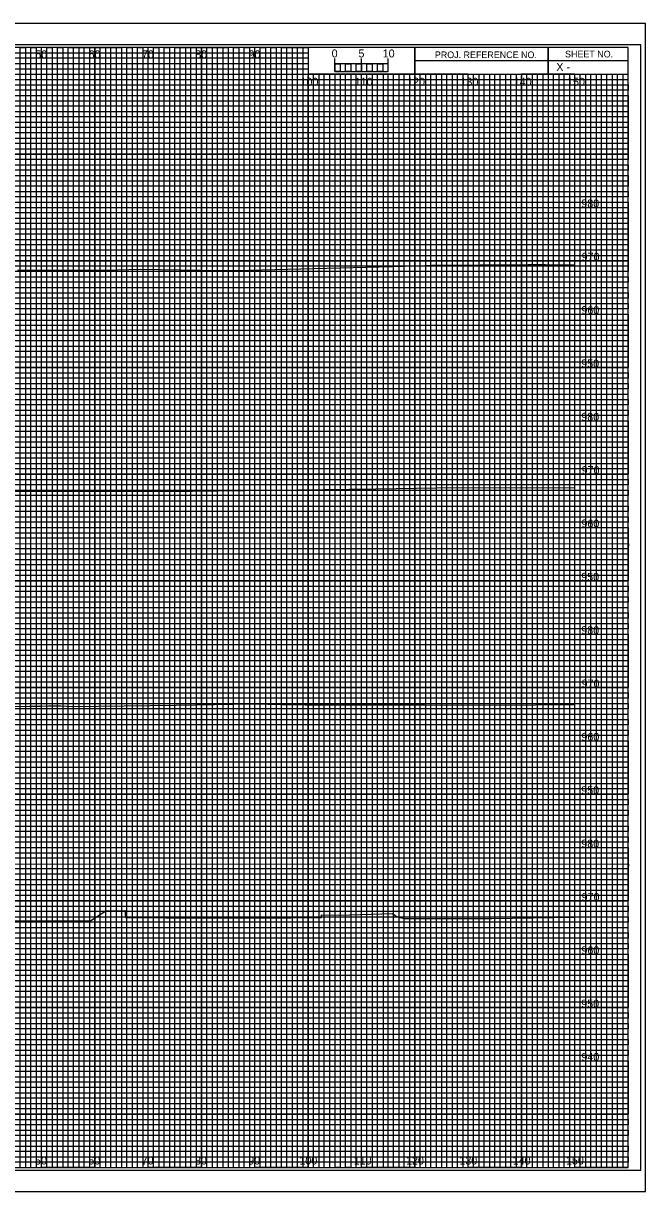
# Model space of a CAD drawing. Extents: x -13 to 760, y -5 to 1491.
# Drawn here: x 206.6 to 323.3, y 952.5 to 1171.5 of the extents above; entities that cross this region are included whole.
import ezdxf

# ---------------------------------------------------------------- set-up
doc = ezdxf.new("R2010")
doc.units = 0
for name, color, linetype in [('Exist XS Ground Line', 7, 'Continuous'), ('Prop XS Elevation Labels', 7, 'Continuous'), ('Prop XS Offset Labels', 7, 'Continuous'), ('Sheet Cross Section CELL', 7, 'Continuous'), ('Sheet Cross Section Grid Major CELL', 7, 'Continuous'), ('Sheet Cross Section Grid Middle CELL', 7, 'Continuous'), ('Sheet Cross Section Grid Minor 1 CELL', 7, 'Continuous'), ('Sheet Cross Section Grid Minor 2 CELL', 7, 'Continuous'), ('Sheet Cross Section Scale CELL', 7, 'Continuous'), ('Sheet Cutting Line CELL', 7, 'Continuous'), ('Sheet DOT Grid CELL', 7, 'Continuous'), ('Sheet Plot Border Inside CELL', 7, 'Continuous'), ('Sheet Plot Border Outside CELL', 7, 'Continuous')]:
    doc.layers.add(name, color=color, linetype=linetype)

msp = doc.modelspace()

# ---------------------------------------------------------------- linework, layer by layer
at = {"layer": 'Exist XS Ground Line'}
for points in [[(205.5, 1125.24), (224.22, 1125.32), (228.53, 1125.43), (243.78, 1125.18), (245.43, 1125.17), (245.61, 1125.17), (246.42, 1125.17), (280.64, 1126.05), (283.2, 1126.18), (301.24, 1126.32), (302.72, 1126.34), (304.49, 1126.33), (310, 1126.25)], [(205.5, 1125.24), (224.22, 1125.32), (228.53, 1125.43), (243.78, 1125.18), (245.43, 1125.17), (245.61, 1125.17), (246.42, 1125.17), (280.64, 1126.05), (283.2, 1126.18), (301.24, 1126.32), (302.72, 1126.34), (304.49, 1126.33), (310, 1126.25)], [(188.63, 1083.76), (217.55, 1083.82), (233.39, 1083.79), (272.72, 1084.24), (284.14, 1084.47), (295.83, 1084.5), (310, 1084.46)], [(188.63, 1083.76), (217.55, 1083.82), (233.39, 1083.79), (272.72, 1084.24), (284.14, 1084.47), (295.83, 1084.5), (310, 1084.46)], [(196.8, 1043.44), (207.77, 1043.51), (210.05, 1043.53), (211.28, 1043.58), (213.62, 1043.59), (215.73, 1043.45), (235.24, 1043.73), (249.69, 1043.94), (255.11, 1043.83), (259.43, 1043.79), (267.91, 1043.74), (281.85, 1043.74), (284.81, 1043.7), (288.81, 1043.8), (295.24, 1043.7), (310, 1043.83)], [(196.8, 1043.44), (207.77, 1043.51), (210.05, 1043.53), (211.28, 1043.58), (213.62, 1043.59), (215.73, 1043.45), (235.24, 1043.73), (249.69, 1043.94), (255.11, 1043.83), (259.43, 1043.79), (267.91, 1043.74), (281.85, 1043.74), (284.81, 1043.7), (288.81, 1043.8), (295.24, 1043.7), (310, 1043.83)], [(201.56, 1003.28), (219.24, 1003.32), (222.07, 1005.14), (222.08, 1005.14), (222.18, 1005.14), (225.68, 1005.22), (225.71, 1004.61), (225.77, 1003.89), (225.78, 1003.89), (228.27, 1003.88), (233.32, 1003.85), (256.76, 1003.85), (262.47, 1003.88), (262.48, 1003.88), (262.51, 1004.43), (265.79, 1004.32), (275.8, 1004.67), (276.7, 1004.01), (278.04, 1003.7), (294.46, 1003.69), (310, 1003.97)], [(201.56, 1003.28), (219.24, 1003.32), (222.07, 1005.14), (222.08, 1005.14), (222.18, 1005.14), (225.68, 1005.22), (225.71, 1004.61), (225.77, 1003.89), (225.78, 1003.89), (228.27, 1003.88), (233.32, 1003.85), (256.76, 1003.85), (262.47, 1003.88), (262.48, 1003.88), (262.51, 1004.43), (265.79, 1004.32), (275.8, 1004.67), (276.7, 1004.01), (278.04, 1003.7), (294.46, 1003.69), (310, 1003.97)]]:
    msp.add_lwpolyline(points, dxfattribs=at)
at = {"layer": 'Sheet Cross Section CELL'}
for p, q in [((305, 1167.01), (305, 1162.01)), ((305, 1162.01), (305, 1167.01)), ((280, 1164.51), (280, 1162.01)), ((320, 1164.5), (280, 1164.5)), ((280, 1162.01), (320, 1162.01))]:
    msp.add_line(p, q, dxfattribs=at)
for points in [[(320, 1167.01), (0, 1167.01), (0, 957.01), (320, 957.01)], [(280, 1167.01), (260, 1167.01), (260, 1162.04), (280, 1162.04)], [(320, 1167.01), (280, 1167.01), (280, 1162.01), (320, 1162.01)]]:
    msp.add_lwpolyline(points, close=True, dxfattribs=at)
at = {"layer": 'Sheet Cross Section Grid Major CELL'}
for p, q in [((210, 1167.01), (200, 1167.01)), ((210, 957.01), (210, 1167.01)), ((230, 1167.01), (220, 1167.01)), ((220, 1167.01), (220, 957.01)), ((230, 957.01), (230, 1167.01)), ((250, 1167.01), (240, 1167.01)), ((240, 1167.01), (240, 957.01)), ((250, 957.01), (250, 1167.01)), ((260, 1167.01), (260, 957.01)), ((270, 957.01), (270, 1162.01)), ((290, 1162.01), (280, 1162.01)), ((280, 1162.01), (280, 957.01)), ((290, 957.01), (290, 1162.01)), ((310, 1162.01), (300, 1162.01)), ((300, 1162.01), (300, 957.01)), ((310, 957.01), (310, 1162.01)), ((220, 957.01), (210, 957.01)), ((240, 957.01), (230, 957.01)), ((260, 957.01), (250, 957.01)), ((280, 957.01), (270, 957.01)), ((300, 957.01), (290, 957.01)), ((320, 957.01), (310, 957.01)), ((320, 957.01), (320, 957.01))]:
    msp.add_line(p, q, dxfattribs=at)
for points in [[(0, 1157.01), (320, 1157.01), (320, 1147.01), (0, 1147.01)], [(0, 1137.01), (320, 1137.01), (320, 1127.01), (0, 1127.01)], [(0, 1117.01), (320, 1117.01), (320, 1107.01), (0, 1107.01)], [(0, 1097.01), (320, 1097.01), (320, 1087.01), (0, 1087.01)], [(0, 1077.01), (320, 1077.01), (320, 1067.01), (0, 1067.01)], [(0, 1057.01), (320, 1057.01), (320, 1047.01), (0, 1047.01)], [(0, 1037.01), (320, 1037.01), (320, 1027.01), (0, 1027.01)], [(0, 1017.01), (320, 1017.01), (320, 1007.01), (0, 1007.01)], [(0, 997.01), (320, 997.01), (320, 987.01), (0, 987.01)], [(0, 977.01), (320, 977.01), (320, 967.01), (0, 967.01)]]:
    msp.add_lwpolyline(points, dxfattribs=at)
at = {"layer": 'Sheet Cross Section Grid Middle CELL'}
for points in [[(205, 957.01), (215, 957.01), (215, 1167.01), (225, 1167.01), (225, 957.01), (235, 957.01), (235, 1167.01), (245, 1167.01), (245, 957.01), (255, 957.01), (255, 1167.01), (259.93, 1167.01), (260, 1167.01), (260, 1162.01), (264.99, 1162.01), (264.99, 957.01), (275, 957.01), (275, 1162.01), (285, 1162.01), (285, 957.01), (295, 957.01), (295, 1162.01), (305, 1162.01), (305, 957.01), (315, 957.01), (315, 1162.01)], [(0, 1162.01), (275, 1162.01)], [(0, 1142.01), (320, 1142.01), (320, 1152.01), (0, 1152.01)], [(0, 1122.01), (320, 1122.01), (320, 1132.01), (0, 1132.01)], [(0, 1102.01), (320, 1102.01), (320, 1112.01), (0, 1112.01)], [(0, 1082.01), (320, 1082.01), (320, 1092.01), (0, 1092.01)], [(0, 1062.01), (320, 1062.01), (320, 1072.01), (0, 1072.01)], [(0, 1042.01), (320, 1042.01), (320, 1052.01), (0, 1052.01)], [(0, 1022.01), (320, 1022.01), (320, 1032.01), (0, 1032.01)], [(0, 1002.01), (320, 1002.01), (320, 1012.01), (0, 1012.01)], [(0, 982.01), (320, 982.01), (320, 992.01), (0, 992.01)], [(0, 962.01), (320, 962.01), (320, 972.01), (0, 972.01)]]:
    msp.add_lwpolyline(points, dxfattribs=at)
at = {"layer": 'Sheet Cross Section Grid Minor 1 CELL'}
for p, q in [((0, 1166.01), (260, 1166.01)), ((260, 1166.01), (260, 1164.99)), ((260, 1164.99), (0, 1164.99)), ((0, 1164.01), (260, 1164.01)), ((260, 1162.9), (0, 1162.9)), ((260, 1164.01), (260, 1162.9)), ((0, 1161.01), (320, 1161.01))]:
    msp.add_line(p, q, dxfattribs=at)
for points in [[(0, 1160.01), (270, 1160.01), (320, 1160.01), (320, 1159.01), (0, 1159.01)], [(0, 1158.01), (320, 1158.01), (320, 1156.01), (0, 1156.01)], [(0, 1155.01), (320, 1155.01), (320, 1154.01), (0, 1153.99)], [(0, 1153.01), (320, 1153.01), (320, 1151.01), (0, 1151.01)], [(0, 1150.01), (320, 1150.01), (320, 1149.01), (0, 1149.01)], [(0, 1148.01), (320, 1148.01), (320, 1146.01), (0, 1146.01)], [(0, 1145.01), (320, 1145.01), (320, 1144.01), (0, 1144.01)], [(0, 1143.01), (320, 1143.01), (320, 1141.01), (0, 1141.01)], [(0, 1140.01), (320, 1140.01), (320, 1139.01), (0, 1139.01)], [(0, 1138.01), (320, 1138.01), (320, 1136.01), (0, 1136.01)], [(0, 1135.01), (320, 1135.01), (320, 1134.01), (0, 1134.01)], [(0, 1133.01), (320, 1133.01), (320, 1130.96), (320, 1130.01), (320, 1129.01), (0, 1129.01)], [(0, 1131.01), (320, 1131.01), (320, 1130.01), (0, 1130.01)], [(0, 1128.01), (320, 1128.01), (320, 1126.01), (0, 1126.04)], [(0, 1126.04), (320, 1126.01), (320, 1125.01), (0, 1125.01)], [(0, 1124.01), (320, 1124.01), (320, 1123.01), (0, 1123.01)], [(0, 1121.01), (320, 1121.01), (320, 1120.01), (0, 1120.01)], [(0, 1119.01), (320, 1119.01), (320, 1118.01), (0, 1118.01)], [(-0.07, 1115.9), (320, 1115.9), (320, 1114.89), (-0.07, 1114.89)], [(0, 1114.01), (320, 1114.01), (320, 1113.01), (0, 1113.01)], [(0, 1111.01), (320, 1111.01), (320, 1110.01), (0, 1110.01)], [(0, 1109.01), (320, 1109.01), (320, 1108.01), (0, 1108.01)], [(0, 1106.01), (320, 1106.01), (320, 1105.01), (0, 1105.01)], [(0, 1104.01), (320, 1104.01), (320, 1103.01), (0, 1103.01)], [(0, 1101.01), (320, 1101.01), (320, 1100.01), (0, 1100.01)], [(0, 1099.01), (320, 1099.01), (320, 1098.01), (0, 1098.01)], [(0, 1096.01), (320, 1096.01), (319.99, 1094.99), (0, 1095.01)], [(0, 1094.01), (320, 1094.01), (320, 1093.01), (0, 1093.01)], [(0, 1091.01), (320, 1091.01), (320, 1090.01), (0, 1090.01)], [(0, 1089.01), (320, 1089.01), (320, 1088.01), (0, 1088.01)], [(0, 1086.01), (320, 1086.01), (320, 1085.01), (0, 1085.01)], [(0, 1084.01), (320, 1084.01), (320, 1083.01), (0, 1083.01)], [(0, 1081.01), (320, 1081.01), (320, 1080.01), (0, 1080.01)], [(0, 1079.01), (320, 1079.01), (320, 1078.01), (0, 1078.01)], [(0, 1076.01), (320, 1076.01), (320, 1075.01), (0, 1075.01)], [(0, 1074), (320.07, 1073.92), (320, 1073.01), (0, 1073.01)], [(0, 1071.01), (320, 1071.01), (320, 1070.01), (0, 1070.01)], [(0, 1069.01), (320, 1069.01), (320, 1068.01), (0, 1068.01)], [(0, 1066.01), (320, 1066.01), (320, 1065.01), (0, 1065.01)], [(0, 1064.01), (320, 1064.01), (320, 1063.01), (0, 1063.01)], [(0, 1061.01), (320, 1061.01), (320, 1060.01), (0, 1060.01)], [(0, 1059.01), (320, 1059.01), (320, 1058.01), (0, 1058.01)], [(0, 1056.01), (320, 1056.01), (320, 1055.01), (0, 1055.01)], [(0, 1054.01), (320, 1054.01), (320, 1053.01), (0, 1053.01)], [(0, 1051.01), (320, 1051.01), (320, 1050.01), (0, 1050.01)], [(0, 1049.01), (320, 1049.01), (320, 1048.01), (0, 1048.01)], [(0, 1046.01), (320, 1046.01), (320, 1045.01), (0, 1045.01)], [(0, 1044.01), (320, 1044.01), (320, 1043.01), (0, 1043.01)], [(0, 1041.01), (320, 1041.01), (320, 1040.01), (0, 1040.01)], [(0, 1039.01), (320, 1039.01), (320, 1038.01), (0, 1038.01)], [(0, 1036.01), (320, 1036.01), (319.99, 1034.99), (0, 1035.01)], [(0, 1034.01), (320, 1034.01), (320, 1033.01), (0, 1033.01)], [(0, 1031.01), (320, 1031.01), (320, 1030.01), (0, 1030.01)], [(0, 1029.01), (320, 1029.01), (320, 1028.01), (0, 1028.01)], [(0, 1026.01), (320, 1026.01), (320, 1025.01), (0, 1025.01)], [(0, 1024.01), (320, 1024.01), (320, 1023.01), (0, 1023.01)], [(0, 1021.01), (320, 1021.01), (320, 1020.01), (0, 1020.01)], [(0, 1019.01), (320, 1019.01), (320, 1018.01), (0, 1018.01)], [(0, 1016.01), (320, 1016.01), (320, 1015.01), (0, 1015.01)], [(0, 1014), (320.07, 1013.92), (320, 1013.01), (0, 1013.01)], [(0, 1011.01), (320, 1011.01), (320, 1010.01), (0, 1010.01)], [(0, 1009.01), (320, 1009.01), (320, 1008.01), (0, 1008.01)], [(0, 1006.01), (320, 1006.01), (320, 1005.01), (0, 1005.01)], [(0, 1004.01), (320, 1004.01), (320, 1003.01), (0, 1003.01)], [(0, 1001.01), (320, 1001.01), (320, 1000.01), (0, 1000.01)], [(0, 999.01), (320, 999.01), (320, 998.01), (0, 998.01)], [(0, 996.01), (320, 996.01), (320, 995.01), (0, 995.01)], [(0, 994.01), (320, 994.01), (320, 993.01), (0, 993.01)], [(0, 991.01), (320, 991.01), (320, 990.01), (0, 990.01)], [(0, 989.01), (320, 989.01), (320, 988.01), (0, 988.01)], [(0, 986.01), (320, 986.01), (320, 985.01), (0, 985.01)], [(0, 984.01), (320, 984.01), (320, 983.01), (0, 983.01)], [(0, 981.01), (320, 981.01), (320, 980.01), (0, 980.01)], [(0, 979.01), (320, 979.01), (320, 978.01), (0, 978.01)], [(0, 976.01), (320, 976.01), (320, 975.01), (0, 975.01)], [(0, 974.01), (320, 974.01), (320, 973.01), (0, 973.01)], [(0, 971.01), (320, 971.01), (320, 970.01), (0, 970.01)], [(0, 969.01), (320, 969.01), (320, 968.01), (0, 968.01)], [(0, 966.01), (320, 966.01), (320, 965.01), (0, 965.01)], [(0, 964.01), (320, 964.01), (320, 963.01), (0, 963.01)], [(0, 961.01), (320, 961.01), (320, 960.01), (0, 960.01)], [(0, 959.01), (320, 959.01), (320, 958.01), (0, 958.01)]]:
    msp.add_lwpolyline(points, dxfattribs=at)
at = {"layer": 'Sheet Cross Section Grid Minor 2 CELL'}
for p, q in [((267, 1162.01), (266.01, 1162.01)), ((266.01, 1162.01), (266.01, 957.01)), ((267, 957.01), (267, 1162.01)), ((269, 1162.01), (268, 1162.01)), ((268, 1162.01), (268, 957.01)), ((269, 957.01), (269, 1162.01)), ((266.01, 957.01), (265, 957.01)), ((268, 957.01), (267, 957.01))]:
    msp.add_line(p, q, dxfattribs=at)
for points in [[(205, 957.01), (206, 957.01), (206, 1167.01), (207, 1167.01), (207, 957.01)], [(207, 957.01), (208, 957.01), (208, 1167.01), (209, 1167.01), (209, 957.01)], [(210, 957.01), (211, 957.01), (211, 1167.01), (212, 1167.01), (212, 957.01)], [(212, 957.01), (213, 957.01), (213, 1167.01), (214, 1167.01), (214, 957.01)], [(215, 957.01), (216, 957.01), (216, 1167.01), (217, 1167.01), (217, 957.01)], [(217, 957.01), (218, 957.01), (218, 1167.01), (219, 1167.01), (219, 957.01)], [(220, 957.01), (221, 957.01), (221, 1167.01), (222, 1167.01), (222, 957.01)], [(222, 957.01), (223, 957.01), (223, 1167.01), (224, 1167.01), (224, 957.01)], [(225, 957.01), (226, 957.01), (226, 1167.01), (227, 1167.01), (227, 957.01)], [(227, 957.01), (228, 957.01), (228, 1167.01), (229, 1167.01), (229, 957.01)], [(230, 957.01), (231, 957.01), (231, 1167.01), (232, 1167.01), (232, 957.01)], [(232, 957.01), (233, 957.01), (233, 1167.01), (234, 1167.01), (234, 957.01)], [(235, 957.01), (236, 957.01), (236, 1167.01), (237, 1167.01), (237, 957.01)], [(237, 957.01), (238, 957.01), (238, 1167.01), (239, 1167.01), (239, 957.01)], [(240, 957.01), (241, 957.01), (241, 1167.01), (242, 1167.01), (242, 957.01)], [(242, 957.01), (243, 957.01), (243, 1167.01), (244, 1167.01), (244, 957.01)], [(245, 957.01), (246, 957.01), (246, 1167.01), (247, 1167.01), (247, 957.01)], [(247, 957.01), (248, 957.01), (248, 1167.01), (249, 1167.01), (249, 957.01)], [(250, 957.01), (251, 957.01), (251, 1167.01), (252, 1167.01), (252, 957.01)], [(252, 957.01), (253, 957.01), (253, 1167.01), (254, 1167.01), (254, 957.01)], [(255, 957.01), (256, 957.01), (256, 1167.01), (257, 1167.01), (257, 957.01)], [(257, 957.01), (258, 957.01), (258, 1167.01), (259, 1167.01), (259, 957.01)], [(260, 957.01), (261, 957.01), (261, 1162.01), (262.02, 1162.01), (262.02, 957.01)], [(262, 957.01), (263, 957.01), (263, 1162.01), (263.99, 1162.01), (263.99, 957.01)], [(270, 957.01), (270.98, 957.01), (270.98, 1162.01), (272, 1162.01), (272, 957.01)], [(272, 957.01), (273, 957.01), (273, 1162.01), (274.05, 1162.01), (274.05, 957.01)], [(275, 957.01), (276, 957.01), (276, 1162.01), (277, 1162.01), (277, 957.01)], [(277, 957.01), (278, 957.01), (278, 1162.01), (279, 1162.01), (279, 957.01)], [(280, 957.01), (281, 957.01), (281, 1162.01), (282, 1162.01), (282, 957.01)], [(282, 957.01), (283, 957.01), (283, 1162.01), (284, 1162.01), (284, 957.01)], [(285, 957.01), (286, 957.01), (286, 1162.01), (287, 1162.01), (287, 957.01)], [(287, 957.01), (288, 957.01), (288, 1162.01), (289, 1162.01), (289, 957.01)], [(290, 957.01), (291, 957.01), (291, 1162.01), (292, 1162.01), (292, 957.01)], [(292, 957.01), (293, 957.01), (293, 1162.01), (294, 1162.01), (294, 957.01)], [(295, 957.01), (296, 957.01), (296, 1162.01), (297, 1162.01), (297, 957.01)], [(297, 957.01), (298, 957.01), (298, 1162.01), (299, 1162.01), (299, 957.01)], [(300, 957.01), (301, 957.01), (301, 1162.01), (302, 1162.01), (302, 957.01)], [(302, 957.01), (303, 957.01), (303, 1162.01), (304, 1162.01), (304, 957.01)], [(305, 957.01), (306, 957.01), (306, 1162.01), (307, 1162.01), (307, 957.01)], [(307, 957.01), (308, 957.01), (308, 1162.01), (309, 1162.01), (309, 957.01)], [(310, 957.01), (311, 957.01), (311, 1162.01), (312, 1162.01), (312, 957.01)], [(312, 957.01), (313, 957.01), (313, 1162.01), (314, 1162.01), (314, 957.01)], [(315, 957.01), (316, 957.01), (316, 1162.01), (317, 1162.01), (317, 957.01)], [(317, 957.01), (318, 957.01), (318, 1162.01), (319, 1162.01), (319, 957.01)]]:
    msp.add_lwpolyline(points, dxfattribs=at)
at = {"layer": 'Sheet Cross Section Scale CELL'}
for p, q in [((265, 1162.5), (265, 1164.91)), ((265, 1163.91), (265, 1164.91)), ((270, 1162.5), (270, 1164.91)), ((275, 1162.5), (275, 1164.91)), ((275, 1163.91), (275, 1164.91))]:
    msp.add_line(p, q, dxfattribs=at)
for points in [[(275, 1163.91), (265, 1163.91), (265, 1162.5), (275, 1162.5)], [(265, 1163.91), (266, 1163.91), (266, 1162.5), (265, 1162.5)], [(267, 1163.91), (268, 1163.91), (268, 1162.5), (267, 1162.5)], [(269, 1163.91), (270, 1163.91), (270, 1162.5), (269, 1162.5)], [(271, 1163.91), (272, 1163.91), (272, 1162.5), (271, 1162.5)], [(273, 1163.91), (274, 1163.91), (274, 1162.5), (273, 1162.5)]]:
    msp.add_lwpolyline(points, close=True, dxfattribs=at)
at = {"layer": 'Sheet Cutting Line CELL'}
for p, q in [((323.3, 1171.51), (-13.4, 1171.51)), ((-13.4, 952.51), (323.3, 952.51))]:
    msp.add_line(p, q, dxfattribs=at)
at = {"layer": 'Sheet DOT Grid CELL'}
for p, q in [((210, 957.01), (210, 1167.01)), ((220, 957.01), (220, 1167.01)), ((230, 957.01), (230, 1167.01)), ((240, 957.01), (240, 1167.01)), ((250, 957.01), (250, 1167.01)), ((260, 957.01), (260, 1161.7)), ((270, 957.01), (270, 1161.7)), ((280, 957.01), (280, 1161.7)), ((290, 957.01), (290, 1161.7)), ((300, 957.01), (300, 1161.7)), ((310, 957.01), (310, 1161.7)), ((0, 1157.01), (320, 1157.01)), ((0, 1147.01), (320, 1147.01)), ((0, 1137.01), (320, 1137.01)), ((0, 1127.01), (320, 1127.01)), ((0, 1117.01), (320, 1117.01)), ((0, 1107.01), (320, 1107.01)), ((0, 1097.01), (320, 1097.01)), ((0, 1087.01), (320, 1087.01)), ((0, 1077.01), (320, 1077.01)), ((0, 1067.01), (320, 1067.01)), ((0, 1057.01), (320, 1057.01)), ((0, 1047.01), (320, 1047.01)), ((0, 1037.01), (320, 1037.01)), ((0, 1027.01), (320, 1027.01)), ((0, 1017.01), (320, 1017.01)), ((0, 1007.01), (320, 1007.01)), ((0, 997.01), (320, 997.01)), ((0, 987.01), (320, 987.01)), ((0, 977.01), (320, 977.01)), ((0, 967.01), (320, 967.01))]:
    msp.add_line(p, q, dxfattribs=at)
at = {"layer": 'Sheet Plot Border Inside CELL'}
msp.add_lwpolyline([(-10.8, 956.51), (322.4, 956.51), (322.4, 1167.51), (-10.8, 1167.51)], close=True, dxfattribs=at)
at = {"layer": 'Sheet Plot Border Outside CELL'}
msp.add_lwpolyline([(-13.4, 952.51), (323.3, 952.51), (323.3, 1171.51), (-13.4, 1171.51)], close=True, dxfattribs=at)

# ---------------------------------------------------------------- texts
at = {"layer": 'Prop XS Elevation Labels'}
for s, p in [('980', (311.24, 1137.01)), ('970', (311.3, 1127.01)), ('960', (311.26, 1117.01)), ('950', (311.22, 1107.01)), ('980', (311.24, 1097.01)), ('970', (311.3, 1087.01)), ('960', (311.26, 1077.01)), ('950', (311.22, 1067.01)), ('980', (311.24, 1057.01)), ('970', (311.3, 1047.01)), ('960', (311.26, 1037.01)), ('950', (311.22, 1027.01)), ('980', (311.24, 1017.01)), ('970', (311.3, 1007.01)), ('960', (311.26, 997.01)), ('950', (311.22, 987.01)), ('940', (311.26, 977.01))]:
    msp.add_text(s, height=1.5, dxfattribs=at).set_placement(p)
at = {"layer": 'Prop XS Offset Labels'}
for s, p in [('50', (208.83, 1164.95)), ('60', (218.83, 1164.95)), ('70', (228.83, 1164.95)), ('80', (238.83, 1164.95)), ('90', (248.83, 1164.95)), ('100', (258.57, 1159.81)), ('110', (268.75, 1159.81)), ('120', (278.57, 1159.81)), ('130', (288.57, 1159.81)), ('140', (298.57, 1159.81)), ('150', (308.57, 1159.81)), ('50', (208.78, 957.6)), ('60', (218.78, 957.6)), ('70', (228.78, 957.6)), ('80', (238.78, 957.6)), ('90', (248.78, 957.6)), ('100', (258.37, 957.6)), ('110', (268.55, 957.6)), ('120', (278.37, 957.6)), ('130', (288.37, 957.6)), ('140', (298.37, 957.6)), ('150', (308.37, 957.6))]:
    msp.add_text(s, height=1.5, dxfattribs=at).set_placement(p)
at = {"layer": 'Sheet Cross Section CELL'}
for s, height, p in [('PROJ. REFERENCE NO.', 1.25, (283.77, 1165)), ('SHEET NO.', 1.25, (308.19, 1165.13)), ('X - ', 1.5, (306.55, 1162.58))]:
    msp.add_text(s, height=height, dxfattribs=at).set_placement(p)
at = {"layer": 'Sheet Cross Section Scale CELL'}
for s, p in [('0', (264.41, 1165.13)), ('5', (269.44, 1165.13)), ('10', (273.99, 1165.13))]:
    msp.add_text(s, height=1.5, dxfattribs=at).set_placement(p)

doc.saveas('drawing.dxf')
